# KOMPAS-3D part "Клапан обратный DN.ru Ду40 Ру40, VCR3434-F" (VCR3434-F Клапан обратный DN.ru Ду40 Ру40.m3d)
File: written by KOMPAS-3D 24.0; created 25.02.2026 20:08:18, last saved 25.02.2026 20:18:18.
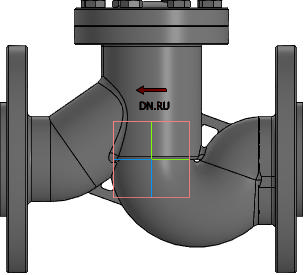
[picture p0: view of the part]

Document properties: Автор: R2D2; Полное имя файла: VCR3434-F Клапан обратный DN.ru Ду40 Ру40.cdw

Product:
- Part/product: Клапан обратный DN.ru Ду40 Ру40  | designation VCR3434-F
    Масса: 8.1
    Раздел спецификации: Прочие изделия
    Форматы листов документа: A3
    Примечание: D100-04054
    additional columns: D100-04054

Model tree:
1. Операция без истории:1
2. Фаска:1  (with: Ребро.Операция без истории:1)
     Угол = 45; Длина 1 = 1; Длина 2 = 1

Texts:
  VCR3434-F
